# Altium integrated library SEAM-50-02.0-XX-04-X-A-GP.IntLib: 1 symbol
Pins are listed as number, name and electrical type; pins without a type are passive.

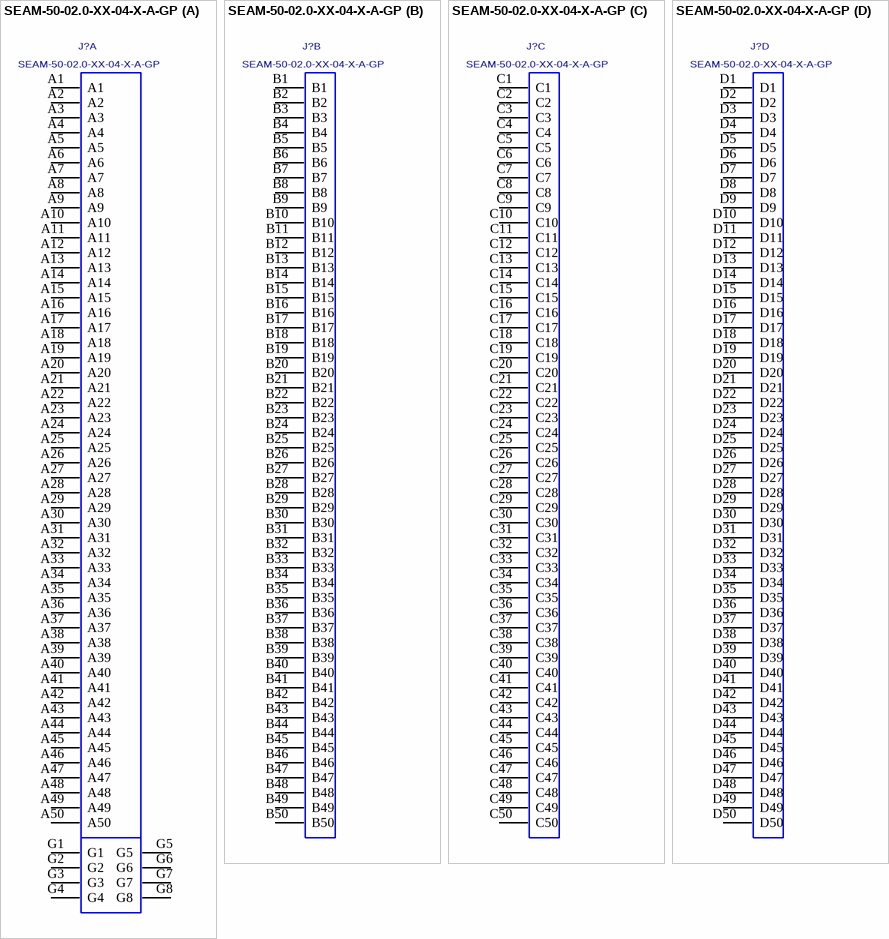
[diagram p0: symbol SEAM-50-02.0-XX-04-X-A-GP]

## SEAM-50-02.0-XX-04-X-A-GP
designator J?
0.050' TERMINAL ARRAY ASSEMBLY; MANUFACTURER: SAMTEC
footprint SEAM-50-02.0-XX-04-X-A-GP
part A pins: A1, A2, A3, A4, A5, A6, A7, A8, A9, A10, A11, A12, A13, A14, A15, A16, A17, A18, A19, A20, A21, A22, A23, A24, A25, A26, A27, A28, A29, A30, A31, A32, A33, A34, A35, A36, A37, A38, A39, A40, A41, A42, A43, A44, A45, A46, A47, A48, A49, A50, G1, G2, G3, G4, G5, G6, G7, G8
part B pins: B1, B2, B3, B4, B5, B6, B7, B8, B9, B10, B11, B12, B13, B14, B15, B16, B17, B18, B19, B20, B21, B22, B23, B24, B25, B26, B27, B28, B29, B30, B31, B32, B33, B34, B35, B36, B37, B38, B39, B40, B41, B42, B43, B44, B45, B46, B47, B48, B49, B50
part C pins: C1, C2, C3, C4, C5, C6, C7, C8, C9, C10, C11, C12, C13, C14, C15, C16, C17, C18, C19, C20, C21, C22, C23, C24, C25, C26, C27, C28, C29, C30, C31, C32, C33, C34, C35, C36, C37, C38, C39, C40, C41, C42, C43, C44, C45, C46, C47, C48, C49, C50
part D pins: D1, D2, D3, D4, D5, D6, D7, D8, D9, D10, D11, D12, D13, D14, D15, D16, D17, D18, D19, D20, D21, D22, D23, D24, D25, D26, D27, D28, D29, D30, D31, D32, D33, D34, D35, D36, D37, D38, D39, D40, D41, D42, D43, D44, D45, D46, D47, D48, D49, D50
